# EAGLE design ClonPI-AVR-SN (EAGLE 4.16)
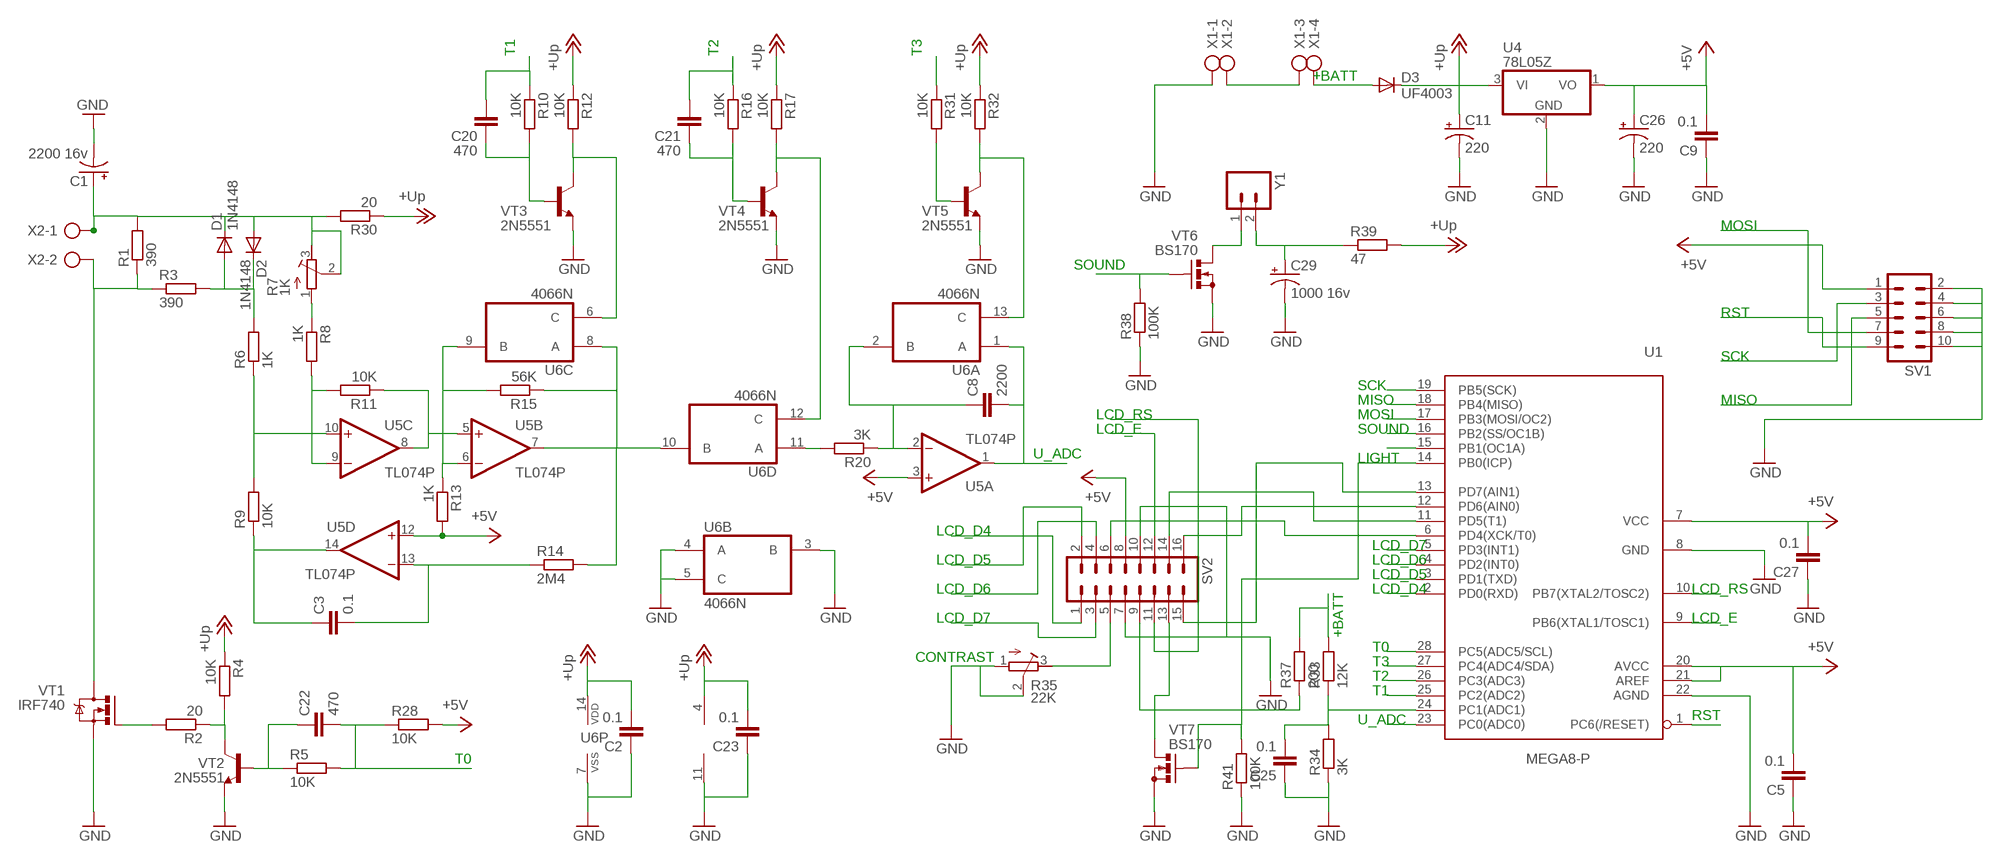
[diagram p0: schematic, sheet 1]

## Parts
C1  2200 16v  CPOL-USE5-10.5  [E5-10,5]
C2  0.1  C-EU050-035X075  [C050-035X075]
C3  0.1  C-EU050-035X075  [C050-035X075]
C5  0.1  C-EU050-035X075  [C050-035X075]
C8  2200  C-EU050-035X075  [C050-035X075]
C9  0.1  C-EU050-035X075  [C050-035X075]
C11  220  CPOL-USE2.5-7  [E2,5-7]
C20  470  C-EU075-032X103  [C075-032X103]
C21  470  C-EU075-032X103  [C075-032X103]
C22  470  C-EU050-035X075  [C050-035X075]
C23  0.1  C-EU050-035X075  [C050-035X075]
C25  0.1  C-EU050-035X075  [C050-035X075]
C26  220  CPOL-USE2.5-7  [E2,5-7]
C27  0.1  C-EU050-035X075  [C050-035X075]
C29  1000 16v  CPOL-USE5-10.5  [E5-10,5]
D1  1N4148  DIODE-D-7.5  [D-7.5]
D2  1N4148  DIODE-D-7.5  [D-7.5]
D3  UF4003  [DO41-10]
R1  390  R-EU_0309/12  [0309/12]
R2  20  R-EU_0207/10  [0207/10]
R3  390  R-EU_0309/12  [0309/12]
R4  10K  R-EU_0207/10  [0207/10]
R5  10K  R-EU_0207/10  [0207/10]
R6  1K  R-EU_0207/10  [0207/10]
R7  1K  R-TRIMM3296Y  [RTRIM3296Y]
R8  1K  R-EU_0207/10  [0207/10]
R9  10K  R-EU_0207/10  [0207/10]
R10  10K  R-EU_0207/10  [0207/10]
R11  10K  R-EU_0207/10  [0207/10]
R12  10K  R-EU_0207/10  [0207/10]
R13  1K  R-EU_0207/10  [0207/10]
R14  2M4  R-EU_0207/12  [0207/12]
R15  56K  R-EU_0207/10  [0207/10]
R16  10K  R-EU_0207/10  [0207/10]
R17  10K  R-EU_0207/10  [0207/10]
R20  3K  R-EU_0207/10  [0207/10]
R28  10K  R-EU_0207/10  [0207/10]
R30  20  R-EU_0207/10  [0207/10]
R31  10K  R-EU_0207/10  [0207/10]
R32  10K  R-EU_0207/10  [0207/10]
R33  12K  R-EU_0207/10  [0207/10]
R34  3K  R-EU_0207/10  [0207/10]
R35  22K  R-TRIMM64W  [RTRIM64W]
R37  200  R-EU_0309/12  [0309/12]
R38  100K  R-EU_0207/10  [0207/10]
R39  47  R-EU_0207/10  [0207/10]
R41  100K  R-EU_0207/10  [0207/10]
SV1  ML10  [ML10]
SV2  ML16  [ML16]
U1  MEGA8-P  [DIL28-3]
U4  78L05Z  [TO92]
U5  TL074P  [DIL14]
U6  4066N  [DIL14]
VT1  IRF740  [TO220BV]
VT2  2N5551  2N5551-NPN-TO92-CBE  [TO92-CBE]
VT3  2N5551  2N5551-NPN-TO92-CBE  [TO92-CBE]
VT4  2N5551  2N5551-NPN-TO92-CBE  [TO92-CBE]
VT5  2N5551  2N5551-NPN-TO92-CBE  [TO92-CBE]
VT6  BS170  [SOT54E]
VT7  BS170  [SOT54E]
X1  AK500/4  [AK500/4]
X2  AK500/2  [AK500/2]
Y1  M02  [02P]

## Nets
+5V: C5.2 C9.2 C26.+ C27.2 R13.2 R28.2 SV1.1 SV2.8 U1.7(VCC) U1.20(AVCC) U1.21(AREF) U4.1(VO) U5.3(A:+IN) U5.12(D:+IN)
+12V: C2.2 C11.+ C23.2 D3.C R4.1 R12.1 R17.1 R30.1 R32.1 R39.2 U4.3(VI) U5.4(P:V+) U6.14(P:VDD) ; supply symbol labelled +Up
+BATT: D3.A R33.2 R37.2 X1.4
GND: C1.- C2.1 C5.1 C9.1 C11.- C23.1 C25.1 C26.- C27.1 C29.- R34.1 R35.1(E) R35.2(S) R38.1 R41.1 SV1.2 SV1.4 SV1.6 SV1.8 SV1.10 SV2.7 SV2.10 U1.8(GND) U1.22(AGND) U4.2(GND) U5.11(P:V-) U6.3(B:B) U6.4(B:A) U6.5(B:C) U6.7(P:VSS) VT1.S VT2.E VT3.E VT4.E VT5.E VT6.S VT7.S X1.1
LCD_D4: SV2.1 U1.2(PD0(RXD))
LCD_D5: SV2.2 U1.3(PD1(TXD))
LCD_D6: SV2.4 U1.4(PD2(INT0))
LCD_D7: SV2.3 U1.5(PD3(INT1))
LCD_E: SV2.12 U1.9(PB6(XTAL1/TOSC1))
LCD_RS: SV2.11 U1.10(PB7(XTAL2/TOSC2))
LIGHT: R41.2 U1.14(PB0(ICP)) VT7.G
MISO: SV1.5 U1.18(PB4(MISO))
MOSI: SV1.7 U1.17(PB3(MOSI/OC2))
N$1: C1.+ D1.C D2.A R1.2 R7.2(S) R7.3(A) R30.2 X2.1
N$2: R1.1 R3.1 VT1.D X2.2
N$3: D1.A D2.C R3.2 R6.2
N$4: R13.1 R15.2 U5.6(B:-IN) U6.9(C:B)
N$5: R7.1(E) R8.1
N$6: R6.1 R9.2 U5.10(C:+IN)
N$7: C3.1 R9.1 U5.14(D:OUT)
N$8: R8.2 R11.2 U5.9(C:-IN)
N$9: R11.1 U5.5(B:+IN) U5.8(C:OUT)
N$10: R14.2 R15.1 U5.7(B:OUT) U6.8(C:A) U6.10(D:B)
N$11: R12.2 U6.6(C:C) VT3.C
N$12: C3.2 R14.1 U5.13(D:-IN)
N$13: C20.1 R10.2 VT3.B
N$14: R37.1 SV2.9
N$15: R17.2 U6.12(D:C) VT4.C
N$16: C21.1 R16.2 VT4.B
N$17: R32.2 U6.13(A:C) VT5.C
N$18: VT6.D Y1.1
N$19: R31.2 VT5.B
N$20: C29.+ R39.1 Y1.2
N$21: R20.2 U6.11(D:A)
N$22: C8.1 R20.1 U5.2(A:-IN) U6.2(A:B)
N$23: X1.2 X1.3
N$24: C22.1 R5.1 VT2.B
N$25: C25.2 R33.1 R34.2 U1.24(PC1(ADC1))
N$26: R2.1 R4.2 VT2.C
N$27: R2.2 VT1.G
N$28: SV2.13 VT7.D
N$40: U1.15(PB1(OC1A))
N$42: SV2.15 U1.13(PD7(AIN1))
N$43: SV2.16 U1.12(PD6(AIN0))
N$44: SV2.14 U1.11(PD5(T1))
N$45: SV2.6 U1.6(PD4(XCK/T0))
N$55: R35.3(A) SV2.5
RST: SV1.9 U1.1(PC6(/RESET))
SCK: SV1.3 U1.19(PB5(SCK))
SOUND: R38.2 U1.16(PB2(SS/OC1B)) VT6.G
T0: C22.2 R5.2 R28.1 U1.28(PC5(ADC5/SCL))
T1: C20.2 R10.1 U1.25(PC2(ADC2))
T2: C21.2 R16.1 U1.26(PC3(ADC3))
T3: R31.1 U1.27(PC4(ADC4/SDA))
U_ADC: C8.2 U1.23(PC0(ADC0)) U5.1(A:OUT) U6.1(A:A)

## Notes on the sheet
- T1 | T2 | T3
- +BATT
- MOSI
- SOUND
- RST
- SCK
- SCK
- MISO | MISO
- LCD_RS | MOSI
- LCD_E | SOUND
- U_ADC
- LIGHT
- LCD_D4
- LCD_D7
- LCD_D5 | LCD_D6
- LCD_D5
- LCD_D6 | LCD_D4 | LCD_RS
- LCD_D7 | LCD_E
- +BATT
- CONTRAST | T0
- T3
- T2
- T1
- RST
- U_ADC
- T0

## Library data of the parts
C1 C11 C26 C29 = rcl:CPOL-US: POLARIZED CAPACITOR, American symbol
C2 C3 C5 C8 C9 C20-C23 C25 C27 = rcl:C-EU: CAPACITOR, European symbol
D1 D2 = diode:DIODE-: DIODE
D3 = diode:UF4003: DIODE
R1-R6 R8-R17 R20 R28 R30-R34 R37-R39 R41 = rcl:R-EU_: RESISTOR, European symbol
R7 R35 = rcl:R-TRIMM: Trimm resistor
SV1 = con-harting-ml:ML10: HARTING
SV2 = con-harting-ml:ML16: HARTING
U1 = atmel:MEGA8-P: MICROCONTROLLER 8 Kbytes FLASH 1 kbytes SRAM 512 bytes EEPROM USART 4-channel 10 bit ADC 2-channel 8 bit ADC Source: avr.lbr
U4 = linear:78*: Positive VOLTAGE REGULATOR Source: http://cache.national.com/ds/LM/LM78L05.pdf http://www.fairchildsemi.com/ds/LM/LM7805.pdf
U5 = linear:TL074: OP AMP
U6 = 40xx:4066: Quad bilateral ANALOG SWITCH
VT1 = transistor-power:IRF740: N-CHANNEL MOS FET
VT2-VT5 = transistor:*-NPN-: NPN Transistror
VT6 VT7 = transistor-small-signal:BS170: N-CHANNEL MOS FET
X1 = con-ptr500:AK500/4: CONNECTOR
X2 = con-ptr500:AK500/2: CONNECTOR
Y1 = con-amp-quick:M02: AMP QUICK CONNECTOR

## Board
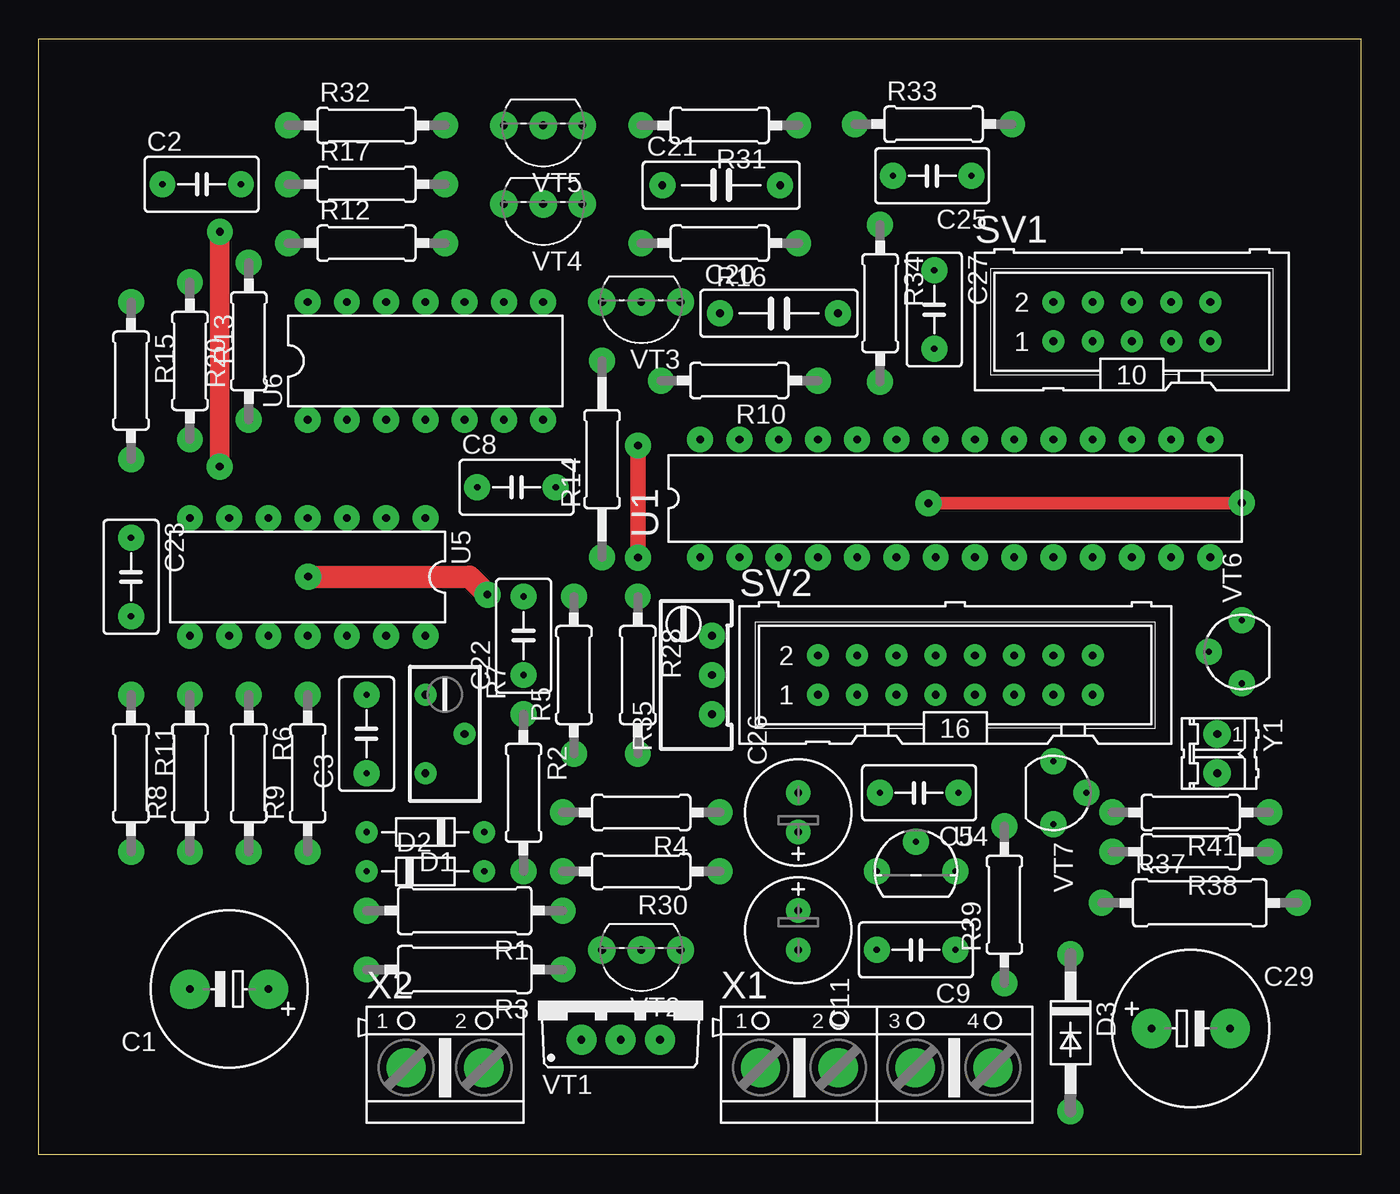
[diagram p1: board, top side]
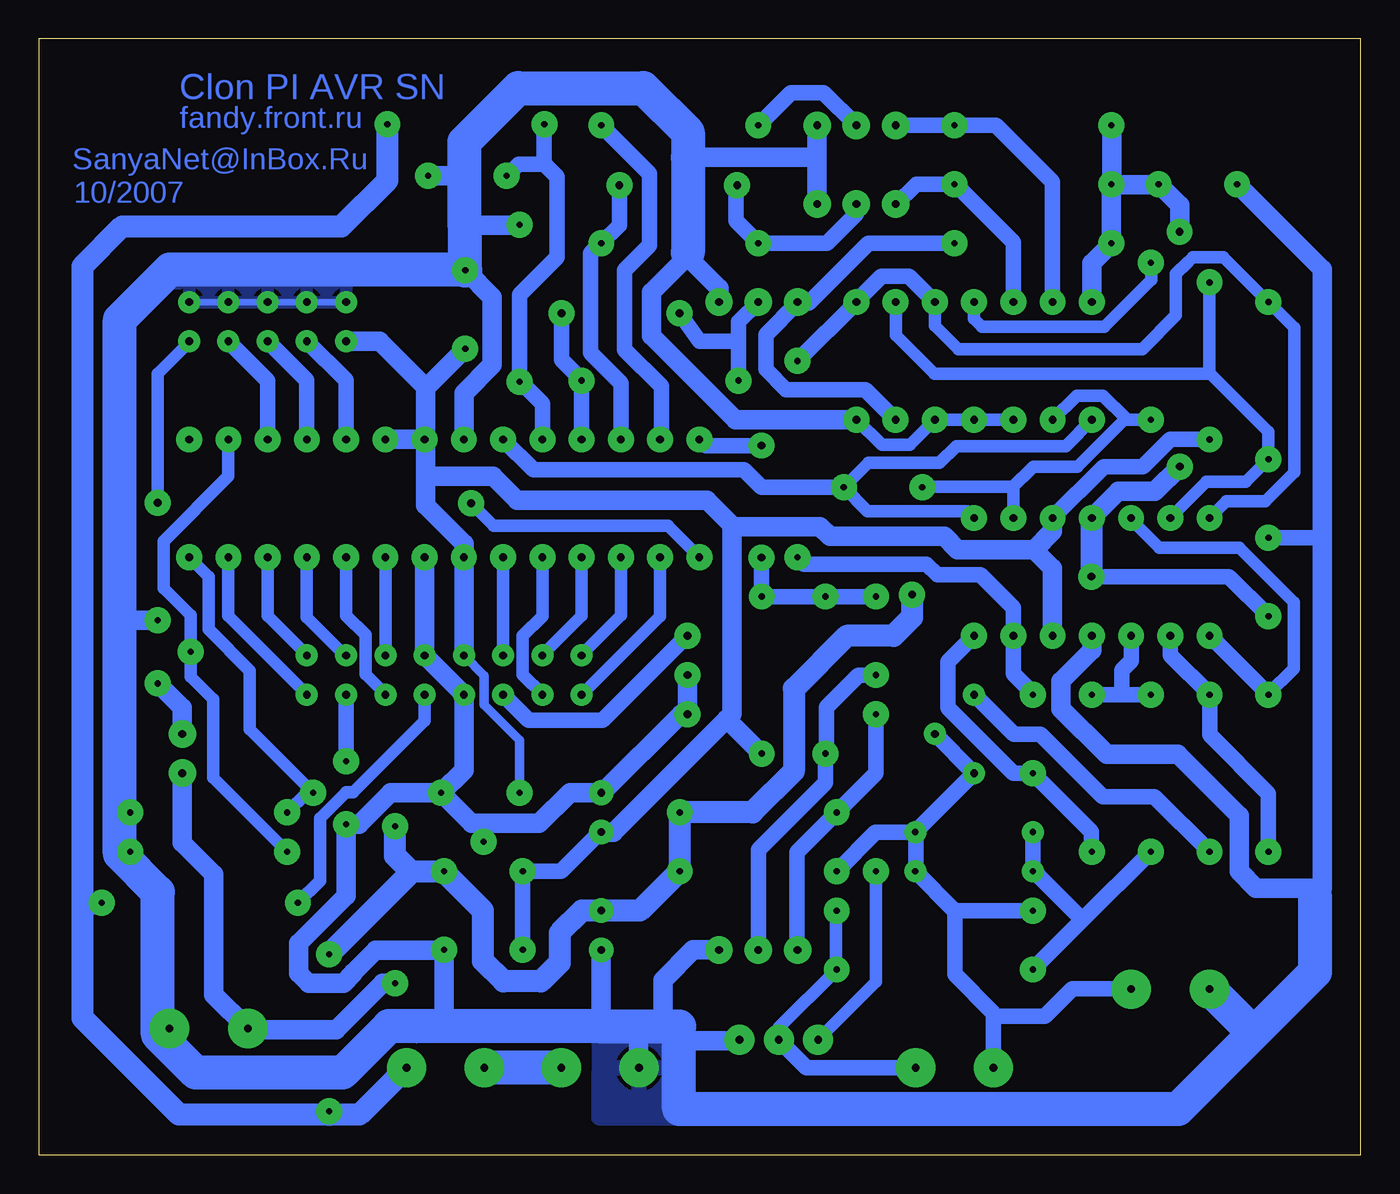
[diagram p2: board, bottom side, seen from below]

Size 85.57 x 72.22 mm. Coordinates in mm from the lower left corner, seen from the top.
Outline: 0,72.22 85.57,72.22 85.57,0 0,0 0,72.22
Copper layers (1*16): Top 0.035mm / dielectric 1.5mm / Bottom 0.035mm
Design rules "default": minimum track width 10mil, minimum drill 24mil, track to track 8mil, track to pad 8mil, pad to pad 8mil, via to via 8mil, smd to smd 8mil, copper to edge 40mil, drill to drill 8mil, minimum pad ring 10mil, minimum via ring 8mil, stop-mask expansion 4mil, vias tented up to drill 0mil, thermal gap 10mil

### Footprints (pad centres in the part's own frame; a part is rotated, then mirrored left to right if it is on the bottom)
E5-10,5 = drill 0.5 pad 2.54 round: + -2.54,0; - 2.54,0
C050-035X075 = drill 0.4 pad 1.676 round: 1 -2.54,0; 2 2.54,0
E2,5-7 = drill 0.5 pad 1.6 round: + -1.27,0; - 1.27,0
C075-032X103 = drill 0.5 pad 1.676 round: 1 -3.81,0; 2 3.81,0
D-7.5 = drill 0.4 pad 1.422 round: A 3.81,0; C -3.81,0
DO41-10 = drill 0.4 pad 1.676 round: A 5.08,0; C -5.08,0
0309/12 = drill 0.4 pad 1.676 round: 1 -6.35,0; 2 6.35,0
0207/10 = drill 0.4 pad 1.676 round: 1 -5.08,0; 2 5.08,0
RTRIM3296Y = drill 0.5 pad 1.422 round: 1 1.27,-2.54; 2 -1.27,0; 3 1.27,2.54
0207/12 = drill 0.4 pad 1.676 round: 1 -6.35,0; 2 6.35,0
RTRIM64W = drill 0.5 pad 1.676 round: 1 1.27,-2.54; 2 1.27,0; 3 1.27,2.54
ML10 = drill 0.5 pad 1.422 round: 1 -5.08,-1.27; 2 -5.08,1.27; 3 -2.54,-1.27; 4 -2.54,1.27; 5 0,-1.27; 6 0,1.27; 7 2.54,-1.27; 8 2.54,1.27; 9 5.08,-1.27; 10 5.08,1.27
ML16 = drill 0.5 pad 1.422 round: 1 -8.89,-1.27; 2 -8.89,1.27; 3 -6.35,-1.27; 4 -6.35,1.27; 5 -3.81,-1.27; 6 -3.81,1.27; 7 -1.27,-1.27; 8 -1.27,1.27; 9 1.27,-1.27; 10 1.27,1.27; 11 3.81,-1.27; 12 3.81,1.27; 13 6.35,-1.27; 14 6.35,1.27; 15 8.89,-1.27; 16 8.89,1.27
DIL28-3 = drill 0.5 pad 1.676 round: 1 -16.51,-3.81; 2 -13.97,-3.81; 3 -11.43,-3.81; 4 -8.89,-3.81; 5 -6.35,-3.81; 6 -3.81,-3.81; 7 -1.27,-3.81; 8 1.27,-3.81; 9 3.81,-3.81; 10 6.35,-3.81; 11 8.89,-3.81; 12 11.43,-3.81; 13 13.97,-3.81; 14 16.51,-3.81; 15 16.51,3.81; 16 13.97,3.81; 17 11.43,3.81; 18 8.89,3.81; 19 6.35,3.81; 20 3.81,3.81; 21 1.27,3.81; 22 -1.27,3.81; 23 -3.81,3.81; 24 -6.35,3.81; 25 -8.89,3.81; 26 -11.43,3.81; 27 -13.97,3.81; 28 -16.51,3.81
TO92 = drill 0.4 pad 1.676 round: 1 -2.54,0; 2 0,1.905; 3 2.54,0
DIL14 = drill 0.5 pad 1.676 round: 1 -7.62,-3.81; 2 -5.08,-3.81; 3 -2.54,-3.81; 4 0,-3.81; 5 2.54,-3.81; 6 5.08,-3.81; 7 7.62,-3.81; 8 7.62,3.81; 9 5.08,3.81; 10 2.54,3.81; 11 0,3.81; 12 -2.54,3.81; 13 -5.08,3.81; 14 -7.62,3.81
TO220BV = drill 0.5 pad 1.93 round: D 0,-2.54; G -2.54,-2.54; S 2.54,-2.54
TO92-CBE = drill 0.5 pad 1.778 round: B 0,0; C 2.54,0; E -2.54,0
SOT54E = drill 0.4 pad 1.676 round: D -2.04,0; G 0,2.135; S 2.04,0
AK500/4 = drill 0.5 pad 2.54 round: 1 -7.518,0; 2 -2.489,0; 3 2.489,0; 4 7.518,0
AK500/2 = drill 0.5 pad 2.54 round: 1 -2.515,0; 2 2.515,0
02P = drill 0.5 pad 1.778 round: 1 -1.27,0; 2 1.27,0

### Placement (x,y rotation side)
C1  12.33,10.73 180 top
C2  10.55,62.8 0 top
C3  21.22,27.24 90 top
C5  56.98,23.43 180 top
C8  30.93,43.2 0 top
C9  56.78,13.27 180 top
C11  49.16,14.54 270 top
C20  47.91,54.45 0 top
C21  44.17,62.74 0 top
C22  31.38,33.59 90 top
C23  5.98,37.4 270 top
C25  57.83,63.34 180 top
C26  49.16,22.16 90 top
C27  57.96,54.7 270 top
C29  74.56,8.19 0 top
D1  25.03,20.89 180 top
D2  25.03,18.35 0 top
D3  66.78,7.91 270 top
R1  27.57,15.81 180 top
R2  31.38,23.43 270 top
R3  27.57,12 180 top
R4  39,22.16 180 top
R5  34.64,31.05 90 top
R6  13.6,24.7 270 top
R7  26.3,27.24 180 top
R8  9.79,24.7 90 top
R9  17.41,24.7 90 top
R10  45.35,50.1 180 top
R11  5.98,24.7 270 top
R12  21.22,58.99 0 top
R13  9.79,51.37 270 top
R14  36.46,45.02 90 top
R15  5.98,50.1 270 top
R16  44.08,58.99 180 top
R17  21.22,62.8 0 top
R20  13.6,52.64 90 top
R28  38.78,31.05 270 top
R30  39,18.35 180 top
R31  44.08,66.61 180 top
R32  21.22,66.61 0 top
R33  57.92,66.69 0 top
R34  54.45,55.11 270 top
R35  42.31,31.05 0 top
R37  75.14,16.31 0 top
R38  74.56,19.62 180 top
R39  62.5,16.19 90 top
R41  74.56,22.16 180 top
SV1  70.75,53.91 0 top
SV2  59.32,31.05 0 top
U1  59.32,42.48 0 top
U4  56.78,18.35 0 top
U5  17.41,37.4 180 top
U6  25.03,51.37 0 top
VT1  37.67,9.99 0 top
VT2  39,13.27 180 top
VT3  39,55.18 180 top
VT4  32.65,61.53 180 top
VT5  32.65,66.61 180 top
VT6  77.86,32.55 90 top
VT7  65.67,23.43 270 top
X1  54.24,5.65 0 top
X2  26.3,5.65 0 top
Y1  76.28,25.97 270 top

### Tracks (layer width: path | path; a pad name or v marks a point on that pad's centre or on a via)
+5V
  Bottom 0.61: SV2.8 56.74,31.01 56.74,29.12 54.44,26.82 C5.2
  Bottom 0.813: 19.99,41.21 20.01,41.23
  Bottom 1.016: 54.24,18.32 U4.1 51.76,18.35 49.17,20.94 49.16,20.93 C26.+ | 54.24,18.32 C9.2 | 54.24,18.32 54.2,18.32 | 21.13,39.17 21.16,39.17 21.16,39.16 | 19.95,41.16 19.99,41.21 U5.3 19.95,41.22 19.95,41.23 16.64,44.53 14.1,44.53 12.34,46.29 R13.2 | U1.21 60.62,46.32 60.66,46.29 | U1.20 | U1.21 60.62,46.32 | 60.53,46.26 60.56,46.26 U1.21 | 60.53,49.58 60.48,49.63 60.49,49.64 60.5,49.64
  Bottom 1.27: SV2.8 U1.7 58.05,39.55 60.53,42.03 60.53,43.9 | C26.+ 48.35,20.89 41.05,28.19 | 41.05,28.19 40.7,28.54 40.7,40.65 | 41,28.14 | 41.05,28.19 41,28.14 | R28.2 40.95,28.14 41,28.14 | 40.7,40.65 40.7,40.72 42.32,42.34 54.62,42.34 56.17,43.9 60.53,43.9 | 40.7,40.65 35,40.65 34.36,40.01 26.95,40.01 26.1,39.17 21.16,39.17 | 21.13,39.17 19.95,40.35 19.95,41.16 | U5.12 19.95,37.95 21.16,39.16 | 60.69,46.3 60.68,46.29 U1.21 | 60.51,46.31 60.53,46.29 U1.21 | 60.53,46.29 60.53,46.32 | 60.53,46.29 U1.21 | 60.53,43.9 60.53,46.26 | 60.53,46.26 60.53,46.29 | 60.66,46.29 U1.20 | U1.20 63.17,46.29 | SV1.1 63.5,52.64 60.5,49.64 | 60.48,49.63 C27.2 | 60.53,46.26 60.53,49.58
+12V  (via drill 0.5 pad 1.68)
  Top 1.27: v11.72,44.53 v11.72,59.73 v11.73,59.73
  Top 1.422: v29.05,36.25 27.88,37.42 v17.43,37.42
  Bottom 1.016: R32.1 16.23,66.6 | R32.1 | 16.1,62.76 16.1,62.75 | 16.1,62.76 R17.1 | 16.1,66.55 R32.1 | 16.14,58.95 R12.1 16.12,58.99 16.11,58.98 | 16.1,62.76 16.14,62.72 | 13.08,62.76 13.05,62.79 13.05,62.8 C2.2 13.08,62.8 | v17.43,37.42 8.54,37.42 6.04,34.92
  Bottom 1.27: 59.32,18.33 U4.3 | 61.44,18.33 61.48,18.33 | 49.16,15.83 49.14,15.86 | C11.+ 49.16,15.83 | 49.16,15.83 49.19,15.81 | 44.1,18.36 R30.1 | 44.08,22.19 44.07,22.2 | R4.1 44.08,22.19 | 44.08,22.19 44.1,22.17 | v11.72,44.53 v11.73,44.53 13.34,42.92 13.34,42.93 15.69,42.93 U5.4 | 16.1,66.55 16.1,62.76 13.08,62.76 | 16.14,62.72 R12.1 | U6.14 17.41,57.67 16.11,58.98 | v11.73,59.73 11.73,61.45 13.08,62.8 | 6.04,34.8 6.04,34.76
  Bottom 1.422: U4.3 | D3.C 61.44,18.33 59.32,18.33 56.81,15.82 56.81,12.54 55.5,11.22 53.06,11.22 51.85,12.43 51.85,14.37 50.41,15.81 49.19,15.81 | R39.2 62.5,19.36 61.48,18.33 | C11.+ 46.65,15.81 44.1,18.36 44.1,22.17 | R4.1 39.36,22.16 36.7,24.82 36.7,30.17 33.28,33.58 30.25,33.58 29.05,34.79 v29.05,36.25 | U5.4 17.4,41.2 17.4,37.45 v17.43,37.42 17.47,37.42 | C23.2 6.04,34.8 6.04,34.92
+BATT
  Bottom 0.406: R37.2 81.56,16.31
  Bottom 1.27: 61.86,5.65 X1.4 | D3.A 66.81,2.8
  Bottom 1.422: X1.4 64.8,2.61 66.75,2.61 | 66.75,2.61 76.48,2.61 82.73,8.85 82.73,16.27 | 82.73,16.27 82.73,57.49 80.15,60.07 65.99,60.07 63,63.06 R33.2 | 82.73,16.27 82.74,16.27 | R37.2 81.53,16.27 82.73,16.27 | 66.75,2.61 66.75,2.58 | D3.A 66.75,2.8 66.75,2.61
GND
  Bottom 0.406: SV1.2 SV1.4 SV1.6 SV1.8 SV1.10
  Bottom 0.61: 65.2,11.79 65.2,11.76 | VT7.S
  Bottom 0.813: U6.3 U6.4 U6.5 29.19,45.94 30.99,45.94 32.64,47.58 U6.7 | 35.19,61.45 VT4.E | 35.19,61.45 | 41.54,55.14 VT3.E | 43.65,58.06 43.55,58.06 43.54,58.05 43.52,58.05
  Bottom 1.016: 49.16,8.34 | C11.- | 59.29,8.34 59.29,8.42 59.32,8.42 | 59.3,13.25 59.3,13.24 | SV2.7 | 2.96,16.69 2.97,16.7 2.97,17.27 | 2.51,39.92 2.5,39.92 2.52,39.94 C23.1 | C27.1 | 57.98,60.16 58.01,60.19 | R34.1 54.48,60.16
  Bottom 1.27: R35.2 R35.1 44.01,28.51 49.13,23.39 C26.- | U1.8 SV2.10 SV2.7 | 80.32,22.17 80.4,22.17 80.4,22.16 R41.1 | R38.1 79.63,19.62 79.63,19.48 80.32,19.48 | 80.32,34.58 80.31,34.58 80.31,34.59 VT6.S | 65.2,11.76 65.85,11.11 68.1,11.11 68.73,11.75 68.73,13.71 65.67,16.77 VT7.S 64.82,21.39 62.79,23.42 C5.1 | 49.16,8.34 C11.- | 59.32,8.42 C9.1 59.3,13.25 | 65.2,11.79 63.75,13.24 59.3,13.24 | 44.12,7.41 44.11,7.41 40.21,7.41 VT1.S | VT2.E 43.22,13.27 45.18,11.31 45.18,8.3 45.18,8.22 | X1.1 46.74,5.66 46.74,8.3 | 35.19,64.78 35.19,61.45 | 35.19,64.78 VT5.E | 41.52,55.12 41.54,55.14 41.54,56.07 43.52,58.05 | 43.55,58.38 43.55,58.06 | U6.7 40.49,47.56 45.91,52.98 45.91,55.81 43.65,58.06 | 58.01,63.33 58.19,63.33 58.21,63.34 C25.1 | C5.1 | C5.1 59.5,23.42 | C5.1 | SV2.7 58.05,24.9 C5.1 | C5.1 57.54,21.45 56.78,21.45 | 56.78,21.45 53.18,21.45 51.19,23.44 C26.- | C26.- 49.15,23.44 | 56.78,21.45 56.78,21.39 U4.2 | 35.19,64.78 35.19,64.54 43.55,64.54 | U5.11 17.41,32.65 19.41,30.66 19.41,28.87 16.45,25.91 11.86,25.91 7.88,21.94 7.88,18.34 6.81,17.27 2.97,17.27 2.51,17.27 2.51,17.32 2.51,39.92 2.51,57.3 C2.1 | U1.22 58.05,49.29 56.21,51.13 56.21,55.5 C27.1 | R34.1 54.47,60.19 54.47,60.16 57.98,60.16
  Bottom 2.184: 77.85,7.79 77.85,17.01 80.32,19.48 80.32,22.17 80.32,34.58 80.32,54.04 77.06,57.3 57.98,57.3 | 77.85,7.79 75.39,5.33 65.91,5.33 62.9,8.34 61.13,8.34 | 61.13,8.34 61.08,8.34 | 61.13,8.34 59.29,8.34 49.16,8.34 | 6.93,7.87 11.84,2.97 44.11,2.97 44.11,7.41 44.11,8.3 45.18,8.3 46.74,8.3 49.16,8.3 | X1.1 | 46.71,5.54 X1.1 | 46.74,5.59 46.72,5.61 X1.1 | 49.16,8.3 | 49.16,8.3 49.16,8.34 | 77.12,8.19 77.12,8.21 | 77.12,8.19 C29.- | 77.85,7.79 77.12,7.79 77.12,8.19 | 58.01,60.19 58.01,63.33 58.01,65.54 54.53,69.02 46.43,69.02 43.55,66.15 43.55,64.54 43.55,58.38 | 6.93,7.87 6.99,7.93 C1.- | 6.93,7.87 2.96,11.84 2.96,16.69 | 57.98,60.16 57.98,60.17 | 57.98,60.16 | 57.98,57.3 57.98,60.16 | C27.1 57.98,57.23 57.98,57.3
  pour Bottom: 49.31,2.4 44.31,2.4 44.28,8.25 49.28,8.25 49.31,2.41
  pour Bottom: 78.21,56.8 77.71,57.32 77.13,57.41 76.6,57.41 65.65,57.47 65.64,55.14 75.84,55.16 76.25,56.12
LCD_D4
  Bottom 0.813: SV2.1 45.37,34.84 45.37,38.65
  Bottom 1.016: 45.37,38.65 U1.2
LCD_D5
  Bottom 0.813: U1.3 47.89,34.91 50.46,32.34
  Bottom 1.016: 50.46,32.34 50.45,32.32 SV2.2
LCD_D6
  Bottom 0.813: U1.4 50.43,34.89 53,32.32
  Bottom 1.016: 53.01,32.31 53,32.32 SV2.4
LCD_D7
  Bottom 0.813: U1.5 52.97,34.86 54.24,33.59 54.24,31.08 52.97,29.81 SV2.3
LCD_E
  Bottom 0.813: SV2.12 63.09,32.32 63.13,32.36 U1.9
LCD_RS
  Bottom 0.813: U1.10 65.67,34.89 64.42,33.64 64.42,31.09 63.13,29.8 SV2.11
LIGHT
  Bottom 0.813: U1.14 74.57,37.41 74.57,34 71.9,31.34 71.9,27.53 VT7.G 68.21,23.43 R41.2
MISO
  Bottom 1.016: 68.22,46.27 | U1.18 68.22,46.27 | SV1.5 68.22,50.11 68.22,46.27
MOSI
  Bottom 1.016: 70.74,46.3 | 70.74,46.3 U1.17 | SV1.7 70.74,50.09 70.74,46.3
N$1
  Bottom 1.016: R7.3 25.01,24.68 | R7.3 R7.2 | R7.3 28.77,20.96 28.83,20.96 D1.C 28.82,20.87 | 28.82,20.87 28.81,20.87 | R30.2 31.4,20.87 28.82,20.87 | 28.82,20.87 28.81,20.86 28.81,18.35 D2.A 26.29,15.8 | R1.2 21.13,15.8 | R1.2 | 26.29,15.8 R1.2 | C1.+ 14.89,10.75 18.69,10.75 20.45,8.98 23.79,8.98 | 23.79,8.98 X2.1 | 23.79,8.98 23.79,9.18 26.28,11.68 26.28,15.87 26.29,15.85 26.29,15.8
N$2
  Bottom 0.813: R1.1 33.97,15.76 33.97,11.97 33.95,11.97 R3.1 37.65,8.27 37.65,7.45 VT1.D
  Bottom 1.016: 37.68,7.45 37.72,7.49 | 37.68,7.45 VT1.D | X2.2 35.88,5.65 37.68,7.45
N$3
  Bottom 1.016: D2.C 21.17,18.35 21.16,18.36 18.05,15.25 18.01,15.21 | D2.C | D2.C D1.A | D2.C 21.24,18.33 | 21.25,11.97 R3.2 | 21.25,11.97 18.01,15.21 | 18.01,15.21 R6.2 | 21.29,11.97 21.25,11.97
N$4
  Bottom 0.813: 30.08,55.18 30.08,53.03 27.59,50.54 9.81,50.54 | R13.1 9.81,56.45 9.81,50.54 | 9.81,50.54 9.77,50.54 9.75,50.55 5.98,46.78 R15.2 7.45,43.55 9.99,43.55 U5.6 | U5.6 12.35,41.19 | U5.6
  Bottom 1.016: 30.14,55.22 30.14,55.21 U6.9 30.08,55.18
N$5
  Bottom 1.016: R8.1 13.35,23.18 16.71,23.18 20.75,27.22 22.46,27.22 25.03,29.8 | 25.03,29.8 25.04,29.81 | 25.03,29.8 R7.1
N$6
  Bottom 0.813: R6.1 13.6,29.83
  Bottom 1.016: R6.1 13.58,29.78 | 13.58,29.78 15.48,29.78 | 15.48,29.78 R9.2 | 13.58,29.78 | U5.10 14.87,31.98 15.48,31.38 15.48,29.78
N$7
  Bottom 1.016: U5.14 26.72,31.9 26.72,28.93 22.48,24.69 C3.1 17.45,20.93 17.45,19.6 17.43,19.6 R9.1
N$8
  Bottom 1.016: R11.2 5.98,23.38 9.79,27.19 R8.2 9.79,29.8 12.33,32.34 U5.9
N$9
  Bottom 0.813: R11.1 6.01,29.8 4.35,31.46 4.35,35.77 7.86,39.27 13.03,39.27 14.89,41.13 14.87,41.15 U5.5
  Bottom 1.016: 14.86,41.23 U5.5 | R11.1 6,29.77 6,29.8 U5.8
N$10
  Bottom 0.813: 27.57,55.08 27.57,53.65 26.04,52.12 14.16,52.12 11.96,54.31 11.96,57 11.2,57.76 10.87,58.09 8.89,58.09 R15.1 4.3,53.51 4.3,44.17 6.19,42.28 8.72,42.28 U5.7 | 32.69,55.21 U6.8
  Bottom 1.016: R15.1 5.98,55.17 | 27.57,55.08 U6.10 29.24,56.85 31.04,56.85 32.69,55.21 | R14.2 U6.8
N$11
  Bottom 1.016: VT3.C 36.41,55.18 | R12.2 31.87,58.99 35.75,55.11 36.53,55.11 | 36.53,55.11 36.55,55.11 | VT3.C 36.53,55.11 | U6.6 32.06,49.51 37.2,49.51 38.52,50.82 38.52,53.07 36.45,55.13 36.46,55.14 VT3.C
N$12
  Bottom 1.016: 36.49,38.67 36.51,38.69 | 36.49,38.67 R14.1 | 36.49,38.67 36.04,38.22 28.1,38.22 27.41,37.53 24.61,37.53 22.49,35.41 U5.13 22.49,31.12 21.17,29.8 21.19,29.78 C3.2
N$13
  Bottom 1.016: R10.2 40.27,52.64 | 40.27,52.64 40.27,53.91 VT3.B | C20.1 42.81,52.64 40.27,52.64
N$14
  Bottom 0.813: SV2.9 60.59,28.09 65.23,23.45 65.68,23.45 67.36,21.77 67.36,17.75 R37.1 | R37.1 68.81,16.3 | R37.1
N$15
  Bottom 1.016: U6.12 22.49,59.05 26.24,62.8 R17.2 28.77,62.8 30.11,61.46 | 30.11,61.46 30.13,61.44 | 30.11,61.46 VT4.C
N$16
  Bottom 1.016: VT4.B 32.65,60.88 34.55,58.98 39.01,58.98 | 39.01,58.98 39.03,58.98 | 39.01,58.98 R16.2 40.45,60.43 40.45,62.72 40.38,62.72 C21.1
N$17
  Bottom 1.016: U6.13 19.95,62.95 23.62,66.62 26.11,66.62 26.11,66.61 R32.2 30.14,66.61 | 30.14,66.61 VT5.C | 30.14,66.61 30.17,66.64
N$18
  Bottom 1.016: Y1.1
  Bottom 1.27: VT6.D 76.28,28.93 Y1.1
N$19
  Bottom 1.016: R31.2 36.88,68.73 34.77,68.73 VT5.B
N$20
  Bottom 0.61: 72.01,8.11 72.02,8.12 C29.+
  Bottom 1.016: 72.05,8.18 72.04,8.19 C29.+
  Bottom 1.27: 72.01,8.11 66.31,8.11 63.31,11.1 R39.1 | Y1.2 76.28,20.2 74.23,18.16 74.23,10.37 72.05,8.18
N$21
  Bottom 0.813: U6.11 25.03,54.1 24.52,53.59 16.6,53.59 13.57,56.62 13.57,57.69 R20.2 | R20.2 | R20.2
N$22
  Bottom 0.813: 13.61,47.53 13.6,47.53 R20.1 13.52,47.56 | U6.2 18.39,49.12 16.69,49.12 15.22,47.65 | 15.22,47.65 15.12,47.55 13.53,47.55 13.52,47.56 | 13.52,47.56 13.51,47.57 | C8.1 28.36,43.22 28.36,43.23 22.5,43.23 22.5,43.22 22.49,43.22 22.49,43.12 | 22.49,43.12 U5.2 | 22.49,43.12 22.61,43.12 21.2,44.53 19.06,44.53 | 19.06,44.53 18.88,44.53 | 19.06,44.53 18.34,44.53 15.22,47.65
N$23
  Bottom 0.406: X1.2 51.7,5.65
  Bottom 2.184: X1.2 X1.3
N$24
  Bottom 1.016: C22.1 32.52,31.05 34.6,28.97 34.6,26.01 R5.1 34.64,24.07 38.97,19.74 38.97,13.24 | 38.97,13.24 | VT2.B 38.97,13.24
N$25
  Bottom 1.016: R33.1 52.85,66.73 | R33.1 | 52.8,64.06 52.02,63.28 52.02,58.08 54.45,55.64 R34.2 54.45,50.07 | 52.8,64.06 52.85,64.11 R33.1 | 52.76,64.11 | 52.8,64.06 52.76,64.11 | C25.2 54.53,64.11 52.76,64.11 | 54.45,50.07 54.46,50.08 | U1.24 52.97,48.59 54.45,50.07
N$26
  Bottom 1.016: VT2.C 36.47,13.28 36.49,13.28 36.49,19.59 R4.2 31.38,24.7 R2.1
N$27
  Bottom 0.813: R2.2 31.38,11.2 VT1.G
N$28
  Bottom 0.813: VT7.D 65.71,25.47 65.71,25.48 65.67,25.52
  Bottom 1.016: 65.67,25.52 SV2.13
N$42
  Bottom 0.813: SV2.15 68.19,29.78 73.29,34.88 U1.13
N$43
  Bottom 0.813: SV2.16 68.2,32.34 70.75,34.88 U1.12
N$44
  Bottom 0.813: SV2.14 65.67,32.29 65.69,32.28 68.21,34.8 U1.11
N$45
  Bottom 0.813: 55.51,32.27 SV2.6 | 55.51,32.27 U1.6 | 55.49,32.25 55.51,32.27
N$55
  Bottom 1.016: SV2.5 53.85,28.12 49.07,28.12 43.58,33.61 | 43.58,33.61 | R35.3 43.58,33.61
RST  (via drill 0.5 pad 1.68)
  Top 0.813: v57.59,42.17 77.84,42.17 v77.87,42.19
  Bottom 0.813: U1.1 44.85,40.71 56.13,40.71 v57.59,42.17 | SV1.9 75.83,52.58 77.87,50.54 v77.87,42.19
SCK
  Bottom 1.016: U1.19 65.68,46.27 | U1.19 | SV1.3 65.68,50.11 U1.19
SOUND
  Bottom 0.813: U1.16 73.29,43.89 77.47,39.71 77.47,36.65 75.73,34.91 VT6.G 75.72,30.95 74.27,29.5 74.27,24.41 R38.2
T0  (via drill 0.5 pad 1.68)
  Top 1.016: v38.79,38.65 v38.79,45.9
  Bottom 1.016: C22.2 R5.2 R28.1 38.78,36.16 38.79,36.16 | U1.28 42.42,45.9 v38.79,45.9 | 38.79,36.16 v38.79,38.65 | 38.79,36.16 38.91,36.16
T1
  Bottom 1.016: C20.2 51.72,51.45 50.43,50.15 R10.1 50.47,50.1 50.49,50.08 50.43,50.02 U1.25
T2
  Bottom 1.016: U1.26 47.89,49.94 49.84,51.89 49.84,58.35 49.17,59.02 49.16,59.02 R16.1 | R16.1 49.16,59.11 49.15,59.12 | 49.16,58.97 49.26,58.86 | R16.1 49.16,58.97 | C21.2 47.98,60.14 49.16,58.97
T3
  Bottom 1.016: R31.1 46.03,63.48 46.03,58.86 47.65,57.25 47.65,52.09 45.28,49.72 45.28,46.21 | 45.28,46.21 45.28,46.2 | 45.28,46.21 U1.27
U_ADC
  Bottom 0.813: U6.1 19.11,45.86 26.17,45.86 27.27,44.77 31.87,44.77 33.45,43.2 C8.2 33.47,43.19 31.93,41.65 25.47,41.65 U5.1 | 55.52,46.28 U1.23
  Bottom 1.016: 33.47,43.19 38.8,43.19 39.94,44.32 53.56,44.32 55.52,46.28

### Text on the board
Bottom: Clon PI AVR SN | fandy.front.ru | SanyaNet@InBox.Ru | 10/2007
